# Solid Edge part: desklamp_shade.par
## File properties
Author: adamb
Template: Iso Metric Part.par
Last saved by: adamb
Revision: 8
Application: Solid Edge
Username: adamb
Dokumentum tartalom típus: 0
Sűrűség: 0,000 kg/m^3
Pontosság: 0,990
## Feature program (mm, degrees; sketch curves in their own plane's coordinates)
sketch for "unnamed Protrusion 1" plane through (0, 0, 0) normal (0, 0, 1) x-axis (1, 0, 0)
  circle centre (0, 0) radius 90
extrude "unnamed Protrusion 1" add finite 120 along +normal
sketch for "Kivágás_1" plane through (0, 0, 120) normal (0, 0, 1) x-axis (1, 0, 0)
  circle centre (0, 0) radius 85
extrude "Kivágás_1" cut finite 115 along -normal
sketch for "unnamed Cutout 1" plane through (0, 0, 5) normal (0, 0, 1) x-axis (0, -1, 0)
  circle centre (0, 0) radius 4.5
extrude "unnamed Cutout 1" cut through along -normal
sketch for "unnamed Cutout 2" #1 plane through (0, 0, 0) normal (0, 0, -1) x-axis (0, -1, 0)
  line (7.5, 4) -> (84.9058, 4)
  arc centre (0, 0) radius 85 from (4, 84.9058) to (84.9058, 4) cw
  line (4, 7.5) -> (4, 84.9058)
  arc centre (0, 0) radius 8.5 from (4, 7.5) to (7.5, 4) cw
sketch for "unnamed Cutout 2" #2 plane through (0, 0, 0) normal (0, 0, -1) x-axis (0, -1, 0)
  line (-7.5, -4) -> (-84.9058, -4)
  arc centre (0, 0) radius 85 from (-4, -84.9058) to (-84.9058, -4) cw
  line (-4, -7.5) -> (-4, -84.9058)
sketch for "unnamed Cutout 2" #3 plane through (0, 0, 0) normal (0, 0, -1) x-axis (0, -1, 0)
  line (-7.5, 4) -> (-84.9058, 4)
  arc centre (0, 0) radius 85 from (-84.9058, 4) to (-4, 84.9058) cw
  line (-4, 7.5) -> (-4, 84.9058)
  arc centre (0, 0) radius 8.5 from (-7.5, 4) to (-4, 7.5) cw
sketch for "unnamed Cutout 2" #4 plane through (0, 0, 0) normal (0, 0, -1) x-axis (0, -1, 0)
  line (4, -7.5) -> (4, -84.9058)
  arc centre (0, 0) radius 8.5 from (7.5, -4) to (4, -7.5) cw
  line (7.5, -4) -> (84.9058, -4)
extrude "unnamed Cutout 2" cut through along -normal
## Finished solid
Body 1: solid body, 18 faces, 53 edges, 32 vertices.
  Faces by surface: plane 11, cylinder 7
  Edges by curve: line 32, circle 21
Bounding box of the edges (mm): 180.000 x 180.000 x 120.000, from (-90, -90, 0) to (90, 90, 120).
Cylindrical faces by radius (mm): R4.5 x1, R8.5 x4, R85 x1, R90 x1
Planar faces by outward normal: +x 2, +y 2, +z 2, -x 2, -y 2, -z 1
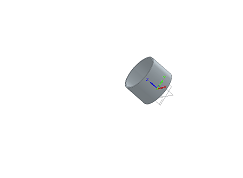
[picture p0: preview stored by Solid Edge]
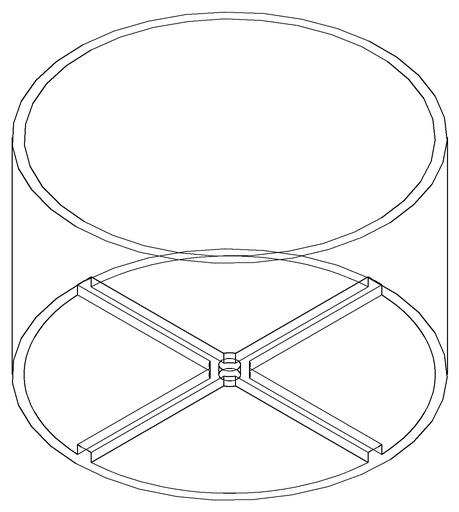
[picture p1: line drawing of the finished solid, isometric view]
